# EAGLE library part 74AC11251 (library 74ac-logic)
1 of 8 DATA SELECTOR/MULTIPLEXER, 3-state
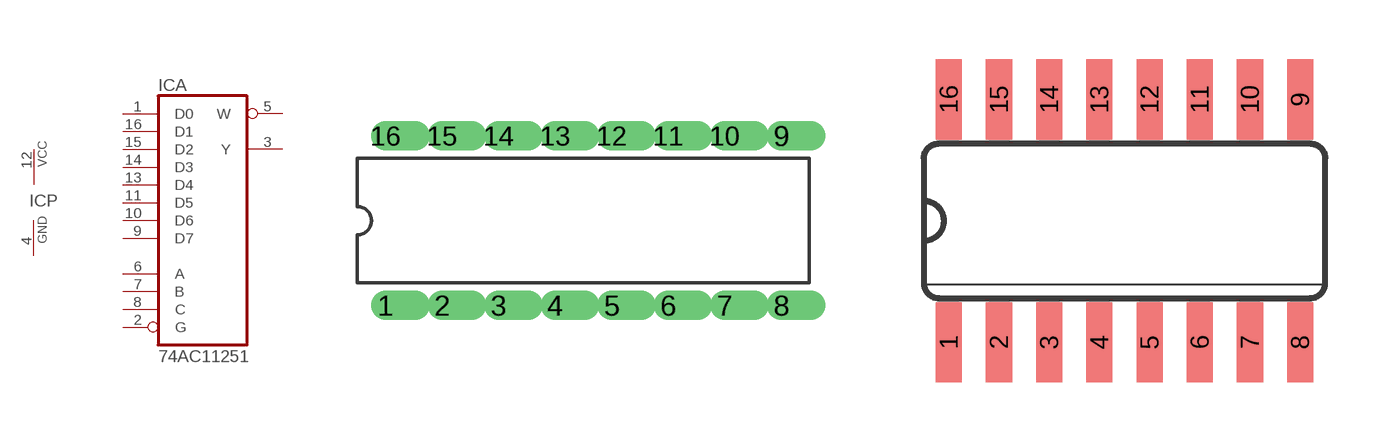
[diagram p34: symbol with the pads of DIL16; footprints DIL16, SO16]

Designator prefix IC; gates A=7411251 P=PWRN

## 74AC11251  [DIL16]
1  A:D0  in
2  A:G  in
3  A:Y  hiz
4  P:GND  pwr
5  A:W  hiz
6  A:A  in
7  A:B  in
8  A:C  in
9  A:D7  in
10  A:D6  in
11  A:D5  in
12  P:VCC  pwr
13  A:D4  in
14  A:D3  in
15  A:D2  in
16  A:D1  in

## 74AC11251D  [SO16]
Pads as for DIL16

## Footprint DIL16 (pad centres in mm)
Dual In Line
drill 0.813 offset: 1 -8.89,-3.81; 2 -6.35,-3.81; 3 -3.81,-3.81; 4 -1.27,-3.81; 5 1.27,-3.81; 6 3.81,-3.81; 7 6.35,-3.81; 8 8.89,-3.81; 9 8.89,3.81; 10 6.35,3.81; 11 3.81,3.81; 12 1.27,3.81; 13 -1.27,3.81; 14 -3.81,3.81; 15 -6.35,3.81; 16 -8.89,3.81

## Footprint SO16 (pad centres in mm)
Small Outline package 150 mil
smd 0.66 x 2.032: 1 -4.445,-3.073; 2 -3.175,-3.073; 3 -1.905,-3.073; 4 -0.635,-3.073; 5 0.635,-3.073; 6 1.905,-3.073; 7 3.175,-3.073; 8 4.445,-3.073; 9 4.445,3.073; 10 3.175,3.073; 11 1.905,3.073; 12 0.635,3.073; 13 -0.635,3.073; 14 -1.905,3.073; 15 -3.175,3.073; 16 -4.445,3.073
